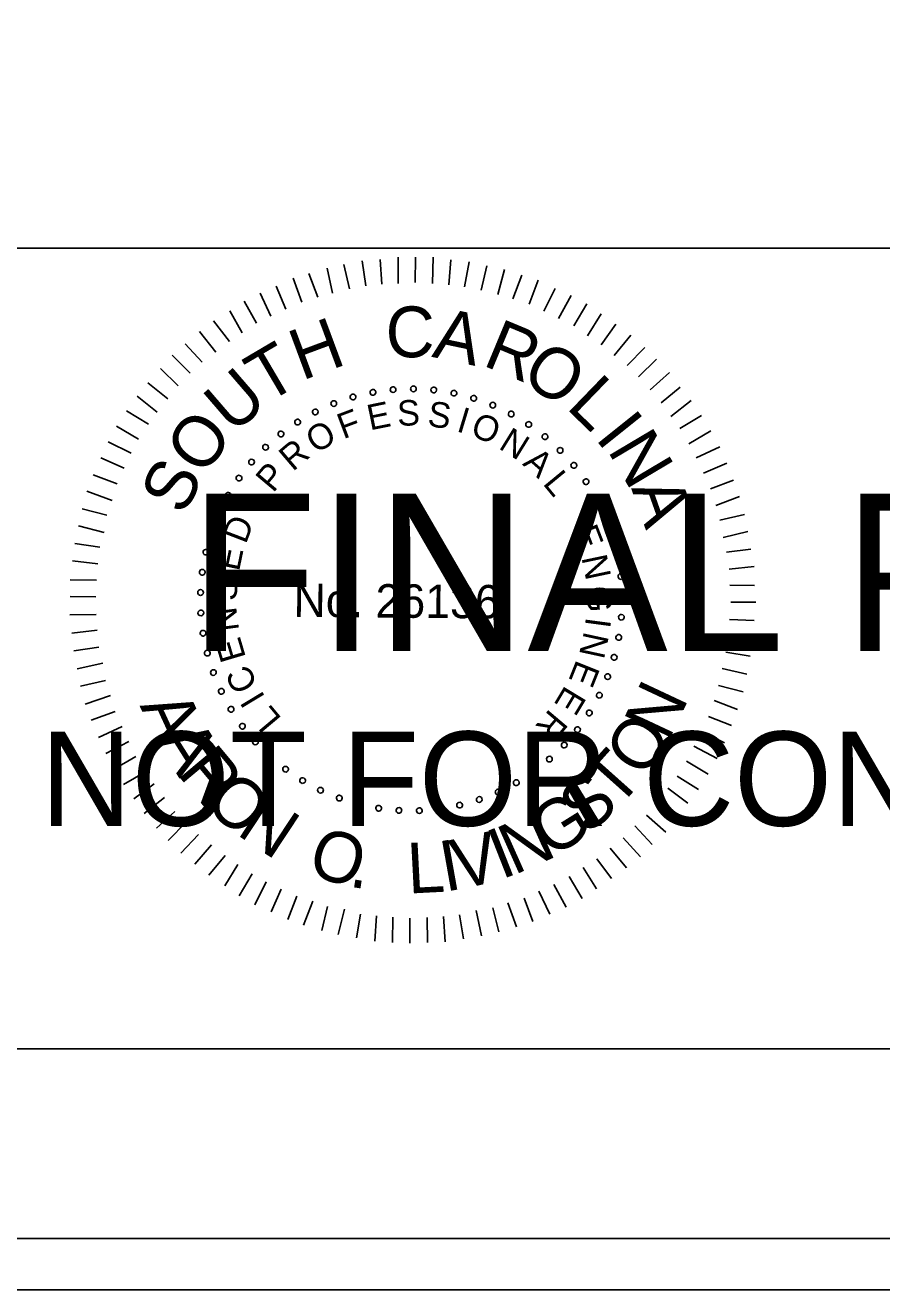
# Model space of a CAD drawing. Extents: x 967 to 1326, y 964 to 3704.
# Drawn here: x 1170.56 to 1189.3, y 2643.72 to 2671.36 of the extents above; entities that cross this region are included whole.
import ezdxf

# ---------------------------------------------------------------- set-up
doc = ezdxf.new("R2010")
doc.units = 0
for name, color, linetype in [('RD_SHT_Bndy', 7, 'Continuous'), ('RD_SHT_IplotShp', 7, 'Continuous'), ('RD_SHT_Misc1', 7, 'Continuous'), ('RD_SHT_Misc2', 7, 'Continuous'), ('RD_XS_TX_Station', 7, 'Continuous')]:
    doc.layers.add(name, color=color, linetype=linetype)

msp = doc.modelspace()

# ---------------------------------------------------------------- linework, layer by layer
at = {"layer": 'RD_SHT_Bndy'}
for p, q in [((996.114, 2666.486), (1323.886, 2666.486)), ((1323.886, 2648.983), (996.114, 2648.983))]:
    msp.add_line(p, q, dxfattribs=at)
at = {"layer": 'RD_SHT_IplotShp'}
for points in [[(967.409, 2643.72), (1326.285, 2643.72), (1326.285, 2863.72), (967.409, 2863.72)], [(988.525, 2644.84), (1326.285, 2644.84), (1326.285, 2862.6), (988.525, 2862.6)]]:
    msp.add_lwpolyline(points, close=True, dxfattribs=at)
at = {"layer": 'RD_SHT_Misc1'}
for p, q in [((1178.01, 2665.663), (1177.93, 2666.209)), ((1178.364, 2665.699), (1178.33, 2666.244)), ((1178.717, 2665.719), (1178.722, 2666.295)), ((1179.093, 2665.739), (1179.098, 2666.292)), ((1179.469, 2665.713), (1179.489, 2666.288)), ((1179.829, 2665.687), (1179.872, 2666.231)), ((1180.174, 2665.646), (1180.271, 2666.19)), ((1176.964, 2665.419), (1176.769, 2665.935)), ((1177.287, 2665.508), (1177.169, 2666.054)), ((1177.657, 2665.597), (1177.53, 2666.128)), ((1180.535, 2665.573), (1180.662, 2666.102)), ((1180.902, 2665.478), (1181.045, 2666.022)), ((1181.231, 2665.384), (1181.428, 2665.896)), ((1176.264, 2665.156), (1176.053, 2665.657)), ((1176.61, 2665.306), (1176.423, 2665.83)), ((1181.584, 2665.265), (1181.78, 2665.786)), ((1181.905, 2665.109), (1182.154, 2665.606)), ((1175.624, 2664.846), (1175.352, 2665.332)), ((1175.933, 2665.005), (1175.699, 2665.506)), ((1182.226, 2664.953), (1182.506, 2665.45)), ((1175.308, 2664.634), (1175.036, 2665.12)), ((1182.562, 2664.789), (1182.85, 2665.27)), ((1182.86, 2664.572), (1183.163, 2665.053)), ((1175.03, 2664.445), (1174.681, 2664.9)), ((1183.158, 2664.378), (1183.484, 2664.828)), ((1174.729, 2664.217), (1174.372, 2664.665)), ((1183.447, 2664.145), (1183.811, 2664.587)), ((1174.435, 2663.997), (1174.062, 2664.399)), ((1183.729, 2663.92), (1184.116, 2664.316)), ((1174.172, 2663.753), (1173.776, 2664.148)), ((1183.98, 2663.672), (1184.368, 2664.061)), ((1173.909, 2663.479), (1173.52, 2663.858)), ((1184.232, 2663.394), (1184.657, 2663.767)), ((1173.684, 2663.197), (1173.242, 2663.546)), ((1184.475, 2663.108), (1184.892, 2663.45)), ((1173.451, 2662.9), (1173.009, 2663.256)), ((1184.687, 2662.807), (1185.128, 2663.156)), ((1173.257, 2662.64), (1172.776, 2662.936)), ((1184.885, 2662.544), (1185.355, 2662.832)), ((1173.039, 2662.312), (1172.559, 2662.6)), ((1185.081, 2662.213), (1185.56, 2662.493)), ((1172.883, 2662.006), (1172.379, 2662.256)), ((1185.24, 2661.904), (1185.756, 2662.145)), ((1172.727, 2661.677), (1172.215, 2661.904)), ((1185.399, 2661.573), (1185.907, 2661.791)), ((1172.571, 2661.333), (1172.051, 2661.53)), ((1172.461, 2660.974), (1171.91, 2661.178)), ((1185.549, 2661.226), (1186.057, 2661.414)), ((1185.669, 2660.865), (1186.185, 2661.06)), ((1172.351, 2660.652), (1171.807, 2660.787)), ((1185.759, 2660.541), (1186.297, 2660.667)), ((1172.286, 2660.276), (1171.727, 2660.419)), ((1185.832, 2660.165), (1186.371, 2660.298)), ((1172.191, 2659.955), (1171.647, 2660.029)), ((1185.906, 2659.842), (1186.436, 2659.906)), ((1172.15, 2659.587), (1171.598, 2659.653)), ((1185.964, 2659.473), (1186.51, 2659.53)), ((1172.124, 2659.234), (1171.548, 2659.239)), ((1185.977, 2659.12), (1186.514, 2659.115)), ((1172.105, 2658.866), (1171.545, 2658.871)), ((1185.997, 2658.751), (1186.542, 2658.747)), ((1172.118, 2658.482), (1171.542, 2658.471)), ((1172.138, 2658.136), (1171.585, 2658.072)), ((1185.971, 2658.368), (1186.508, 2658.348)), ((1185.952, 2658.022), (1186.497, 2657.949)), ((1172.173, 2657.768), (1171.627, 2657.688)), ((1185.888, 2657.655), (1186.417, 2657.566)), ((1172.262, 2657.414), (1171.701, 2657.296)), ((1185.808, 2657.302), (1186.345, 2657.175)), ((1172.321, 2657.037), (1171.774, 2656.911)), ((1185.729, 2656.926), (1186.265, 2656.792)), ((1172.425, 2656.707), (1171.871, 2656.519)), ((1185.634, 2656.597), (1186.146, 2656.401)), ((1172.53, 2656.36), (1172.007, 2656.173)), ((1185.508, 2656.253), (1186.013, 2656.057)), ((1172.681, 2656.029), (1172.165, 2655.788)), ((1185.352, 2655.924), (1185.857, 2655.675)), ((1172.831, 2655.705), (1172.323, 2655.441)), ((1172.982, 2655.374), (1172.497, 2655.094)), ((1185.188, 2655.603), (1185.7, 2655.33)), ((1185.024, 2655.274), (1185.498, 2654.987)), ((1173.194, 2655.042), (1172.709, 2654.762)), ((1184.822, 2654.946), (1185.288, 2654.658)), ((1173.384, 2654.78), (1172.936, 2654.453)), ((1184.62, 2654.687), (1185.055, 2654.353)), ((1173.612, 2654.478), (1173.164, 2654.129)), ((1184.403, 2654.389), (1184.814, 2654.033)), ((1173.832, 2654.177), (1173.437, 2653.812)), ((1184.155, 2654.092), (1184.574, 2653.72)), ((1174.091, 2653.945), (1173.689, 2653.541)), ((1183.899, 2653.864), (1184.28, 2653.454)), ((1174.35, 2653.674), (1173.97, 2653.263)), ((1174.64, 2653.442), (1174.275, 2653.022)), ((1183.644, 2653.597), (1184.024, 2653.18)), ((1174.937, 2653.209), (1174.58, 2652.782)), ((1183.065, 2653.141), (1183.384, 2652.709)), ((1183.358, 2653.37), (1183.715, 2652.944)), ((1175.212, 2653.014), (1174.932, 2652.549)), ((1182.764, 2652.952), (1183.059, 2652.482)), ((1175.525, 2652.812), (1175.245, 2652.331)), ((1175.83, 2652.633), (1175.588, 2652.136)), ((1182.463, 2652.755), (1182.743, 2652.269)), ((1176.159, 2652.477), (1175.94, 2651.98)), ((1176.503, 2652.321), (1176.307, 2651.816)), ((1181.8, 2652.431), (1182.041, 2651.93)), ((1182.124, 2652.581), (1182.396, 2652.08)), ((1176.855, 2652.211), (1176.651, 2651.69)), ((1177.177, 2652.1), (1177.05, 2651.572)), ((1177.545, 2652.036), (1177.409, 2651.484)), ((1180.791, 2652.07), (1180.926, 2651.54)), ((1181.122, 2652.175), (1181.31, 2651.652)), ((1181.476, 2652.28), (1181.664, 2651.771)), ((1177.897, 2651.933), (1177.808, 2651.412)), ((1178.25, 2651.892), (1178.207, 2651.34)), ((1178.603, 2651.866), (1178.598, 2651.313)), ((1178.978, 2651.84), (1178.974, 2651.295)), ((1179.355, 2651.86), (1179.365, 2651.307)), ((1179.715, 2651.88), (1179.749, 2651.327)), ((1180.061, 2651.915), (1180.149, 2651.393)), ((1180.423, 2652.012), (1180.541, 2651.458))]:
    msp.add_line(p, q, dxfattribs=at)
for centre, start, end in [((1178.168, 2663.337), 10.6038, 190.6038), ((1178.609, 2663.397), 5.0653, 185.0653), ((1178.609, 2663.397), 185.0653, 5.0653), ((1179.055, 2663.414), 359.5268, 179.5268), ((1179.055, 2663.414), 179.5268, 359.5268), ((1179.5, 2663.388), 353.9884, 173.9884), ((1179.5, 2663.388), 173.9884, 353.9884), ((1179.94, 2663.319), 348.4499, 168.4499), ((1177.312, 2663.091), 21.6807, 201.6807), ((1177.312, 2663.091), 201.6807, 21.6807), ((1177.734, 2663.235), 16.1422, 196.1422), ((1177.734, 2663.235), 196.1422, 16.1422), ((1178.168, 2663.337), 190.6038, 10.6038), ((1179.94, 2663.319), 168.4499, 348.4499), ((1180.372, 2663.208), 162.9114, 342.9114), ((1180.372, 2663.208), 342.9114, 162.9114), ((1180.79, 2663.056), 337.373, 157.373), ((1176.906, 2662.908), 27.2191, 207.2191), ((1176.906, 2662.908), 207.2191, 27.2191), ((1180.79, 2663.056), 157.373, 337.373), ((1181.193, 2662.864), 151.8345, 331.8345), ((1181.193, 2662.864), 331.8345, 151.8345), ((1176.52, 2662.686), 32.7576, 212.7576), ((1176.52, 2662.686), 212.7576, 32.7576), ((1181.574, 2662.634), 146.2961, 326.2961), ((1181.574, 2662.634), 326.2961, 146.2961), ((1176.156, 2662.428), 38.2961, 218.2961), ((1176.156, 2662.428), 218.2961, 38.2961), ((1181.932, 2662.368), 140.7576, 320.7576), ((1181.932, 2662.368), 320.7576, 140.7576), ((1175.82, 2662.135), 43.8345, 223.8345), ((1175.82, 2662.135), 223.8345, 43.8345), ((1182.263, 2662.069), 135.2191, 315.2191), ((1182.263, 2662.069), 315.2191, 135.2191), ((1175.513, 2661.812), 49.373, 229.373), ((1175.513, 2661.812), 229.373, 49.373), ((1182.563, 2661.74), 129.6807, 309.6807), ((1182.563, 2661.74), 309.6807, 129.6807), ((1175.239, 2661.461), 54.9114, 234.9114), ((1175.239, 2661.461), 234.9114, 54.9114), ((1182.83, 2661.383), 124.1422, 304.1422), ((1182.83, 2661.383), 304.1422, 124.1422), ((1175, 2661.085), 60.4499, 240.4499), ((1175, 2661.085), 240.4499, 60.4499), ((1183.061, 2661.002), 118.6038, 298.6038), ((1183.061, 2661.002), 298.6038, 118.6038), ((1174.798, 2660.687), 65.9884, 245.9884), ((1174.798, 2660.687), 245.9884, 65.9884), ((1183.255, 2660.601), 113.0653, 293.0653), ((1183.255, 2660.601), 293.0653, 113.0653), ((1174.636, 2660.272), 71.5268, 251.5268), ((1174.636, 2660.272), 251.5268, 71.5268), ((1183.408, 2660.182), 107.5268, 287.5268), ((1183.408, 2660.182), 287.5268, 107.5268), ((1174.514, 2659.843), 77.0653, 257.0653), ((1174.514, 2659.843), 257.0653, 77.0653), ((1183.521, 2659.751), 101.9884, 281.9884), ((1183.521, 2659.751), 281.9884, 101.9884), ((1174.435, 2659.405), 82.6038, 262.6038), ((1174.435, 2659.405), 262.6038, 82.6038), ((1183.592, 2659.311), 96.4499, 276.4499), ((1183.592, 2659.311), 276.4499, 96.4499), ((1174.398, 2658.961), 88.1422, 268.1422), ((1174.398, 2658.961), 268.1422, 88.1422), ((1183.619, 2658.866), 90.9114, 270.9114), ((1183.619, 2658.866), 270.9114, 90.9114), ((1174.404, 2658.515), 93.6807, 273.6807), ((1174.404, 2658.515), 273.6807, 93.6807), ((1183.604, 2658.421), 85.373, 265.373), ((1183.604, 2658.421), 265.373, 85.373), ((1174.453, 2658.072), 99.2191, 279.2191), ((1174.453, 2658.072), 279.2191, 99.2191), ((1183.546, 2657.979), 79.8345, 259.8345), ((1183.546, 2657.979), 259.8345, 79.8345), ((1174.545, 2657.636), 104.7576, 284.7576), ((1174.545, 2657.636), 284.7576, 104.7576), ((1183.445, 2657.545), 74.2961, 254.2961), ((1183.445, 2657.545), 254.2961, 74.2961), ((1174.678, 2657.211), 110.2961, 290.2961), ((1174.678, 2657.211), 290.2961, 110.2961), ((1183.303, 2657.122), 68.7576, 248.7576), ((1183.303, 2657.122), 248.7576, 68.7576), ((1174.852, 2656.8), 115.8345, 295.8345), ((1174.852, 2656.8), 295.8345, 115.8345), ((1183.121, 2656.716), 63.2191, 243.2191), ((1183.121, 2656.716), 243.2191, 63.2191), ((1175.065, 2656.409), 121.373, 301.373), ((1175.065, 2656.409), 301.373, 121.373), ((1182.9, 2656.328), 57.6807, 237.6807), ((1182.9, 2656.328), 237.6807, 57.6807), ((1175.314, 2656.039), 126.9114, 306.9114), ((1175.314, 2656.039), 306.9114, 126.9114), ((1182.643, 2655.964), 52.1422, 232.1422), ((1182.643, 2655.964), 232.1422, 52.1422), ((1175.598, 2655.696), 132.4499, 312.4499), ((1175.598, 2655.696), 312.4499, 132.4499), ((1182.353, 2655.627), 46.6038, 226.6038), ((1182.353, 2655.627), 226.6038, 46.6038), ((1175.914, 2655.381), 137.9884, 317.9884), ((1175.914, 2655.381), 317.9884, 137.9884), ((1182.03, 2655.319), 41.0653, 221.0653), ((1182.03, 2655.319), 221.0653, 41.0653), ((1176.258, 2655.099), 143.5268, 323.5268), ((1176.258, 2655.099), 323.5268, 143.5268), ((1181.68, 2655.043), 35.5268, 215.5268), ((1181.68, 2655.043), 215.5268, 35.5268), ((1176.629, 2654.851), 149.0653, 329.0653), ((1176.629, 2654.851), 329.0653, 149.0653), ((1181.305, 2654.803), 29.9884, 209.9884), ((1181.305, 2654.803), 209.9884, 29.9884), ((1177.021, 2654.639), 154.6038, 334.6038), ((1177.021, 2654.639), 334.6038, 154.6038), ((1177.432, 2654.467), 340.1422, 160.1422), ((1180.908, 2654.6), 24.4499, 204.4499), ((1180.908, 2654.6), 204.4499, 24.4499), ((1177.432, 2654.467), 160.1422, 340.1422), ((1177.858, 2654.335), 165.6807, 345.6807), ((1177.858, 2654.335), 345.6807, 165.6807), ((1178.294, 2654.245), 351.2191, 171.2191), ((1178.294, 2654.245), 171.2191, 351.2191), ((1178.737, 2654.198), 356.7576, 176.7576), ((1179.183, 2654.193), 2.2961, 182.2961), ((1179.627, 2654.232), 7.8345, 187.8345), ((1180.065, 2654.313), 13.373, 193.373), ((1180.065, 2654.313), 193.373, 13.373), ((1180.494, 2654.436), 18.9114, 198.9114), ((1180.494, 2654.436), 198.9114, 18.9114), ((1178.737, 2654.198), 176.7576, 356.7576), ((1179.183, 2654.193), 182.2961, 2.2961), ((1179.627, 2654.232), 187.8345, 7.8345)]:
    msp.add_arc(centre, 0.0627, start, end, dxfattribs=at)
at = {"layer": 'RD_XS_TX_Station'}
msp.add_lwpolyline([(967.409, 2643.72), (1326.285, 2643.72), (1326.285, 2863.72), (967.409, 2863.72)], close=True, dxfattribs=at)

# ---------------------------------------------------------------- texts
at = {"layer": 'RD_SHT_Misc1'}
for s, height, rotation, p in [('C', 1.11, 359.5482, (1178.442, 2664.108)), ('A', 1.11, 348.1981, (1179.439, 2664.115)), ('H', 1.11, 20.3637, (1176.614, 2663.587)), ('R', 1.11, 337.4344, (1180.541, 2663.937)), ('T', 1.11, 30.4992, (1175.828, 2663.072)), ('O', 1.108, 326.5869, (1181.366, 2663.609)), ('U', 1.11, 40.8022, (1175.102, 2662.403)), ('L', 1.11, 315.9488, (1182.373, 2663.003)), ('E', 0.557, 11.4103, (1178.103, 2662.503)), ('S', 0.557, 2.208, (1178.709, 2662.601)), ('S', 0.557, 352.6608, (1179.346, 2662.599)), ('O', 1.11, 52.0267, (1174.435, 2661.474)), ('F', 0.557, 20.6127, (1177.52, 2662.309)), ('I', 0.557, 343.1136, (1179.975, 2662.491)), ('O', 0.557, 338.4392, (1180.274, 2662.401)), ('I', 1.11, 308.6613, (1183.011, 2662.338)), ('O', 0.557, 30.8477, (1176.917, 2661.987)), ('N', 0.557, 328.2042, (1180.896, 2662.12)), ('R', 0.557, 40.3949, (1176.415, 2661.594)), ('N', 1.11, 300.7037, (1183.285, 2662.075)), ('A', 0.557, 318.657, (1181.424, 2661.762)), ('S', 1.108, 63.2511, (1174.029, 2660.619)), ('P', 0.557, 49.9421, (1175.985, 2661.124)), ('L', 0.557, 309.4546, (1181.869, 2661.339)), ('A', 1.11, 289.4792, (1183.814, 2661.243)), ('D', 0.557, 69.0364, (1175.386, 2660.003)), ('E', 0.557, 291.049, (1182.53, 2660.307)), ('E', 0.557, 78.2388, (1175.238, 2659.407)), ('N', 0.557, 281.8466, (1182.728, 2659.726)), ('S', 0.557, 87.786, (1175.187, 2658.772)), ('No. 26136', 0.7311, 359.5268, (1176.429, 2658.43)), ('G', 0.557, 272.2995, (1182.833, 2659.097)), ('N', 0.557, 97.3332, (1175.242, 2658.137)), ('I', 0.557, 262.4084, (1182.83, 2658.437)), ('E', 0.557, 106.5355, (1175.394, 2657.541)), ('N', 0.557, 257.7339, (1182.789, 2658.127)), ('C', 0.557, 116.4266, (1175.661, 2656.938)), ('E', 0.557, 248.1867, (1182.628, 2657.511)), ('N', 1.105, 64.8922, (1184.632, 2655.684)), ('I', 0.557, 121.1011, (1175.823, 2656.67)), ('E', 0.557, 238.9844, (1182.378, 2656.949)), ('A', 1.105, 294.7297, (1173.062, 2656.486)), ('L', 0.557, 129.9595, (1176.187, 2656.204)), ('R', 0.557, 229.782, (1182.041, 2656.435)), ('O', 1.105, 56.2059, (1184.102, 2654.874)), ('A', 1.105, 302.2892, (1173.414, 2655.72)), ('R', 1.105, 309.8487, (1173.865, 2655.007)), ('T', 1.105, 48.2685, (1183.515, 2654.211)), ('O', 1.105, 317.7861, (1174.434, 2654.33)), ('S', 1.105, 40.3311, (1182.842, 2653.636)), ('N', 1.105, 326.4725, (1175.158, 2653.686)), ('G', 1.105, 32.0198, (1182.059, 2653.14)), ('N', 1.105, 24.0824, (1181.252, 2652.776)), ('O', 1.105, 342.3472, (1176.697, 2652.82)), ('V', 1.105, 12.7741, (1180.033, 2652.457)), ('I', 1.105, 21.4605, (1180.976, 2652.681)), ('L', 1.105, 2.9677, (1178.943, 2652.379)), ('I', 1.105, 10.1523, (1179.743, 2652.418)), ('.', 1.105, 351.0336, (1177.623, 2652.536))]:
    msp.add_text(s, height=height, rotation=rotation, dxfattribs=at).set_placement(p)
at = {"layer": 'RD_SHT_Misc2'}
for s, height, p in [('FINAL PLANS', 3.4375, (1174.145, 2657.685)), ('NOT FOR CONSTRUCTION', 2.0625, (1170.901, 2653.86))]:
    msp.add_text(s, height=height, dxfattribs=at).set_placement(p)

doc.saveas('drawing.dxf')
